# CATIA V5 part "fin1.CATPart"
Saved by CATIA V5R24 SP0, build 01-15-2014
Part number: Part2
Bounding box of the stored display mesh (mm): x -74.953 to 135, y -74.946 to 74.946, z -20 to 36.39
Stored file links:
  G:\내 드라이브\04_WORK\00_LECTURE\CAD2020\exam\models\fin1.CATPart
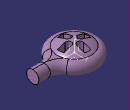
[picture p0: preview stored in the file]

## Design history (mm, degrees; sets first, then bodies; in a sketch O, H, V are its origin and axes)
AxisSystem1: origin (0, 0, 0), X (1, 0, 0), Y (0, 1, 0), Z (0, 0, 1)
Set1
  Sketch1 on YZ plane of AxisSystem1, origin (0, 0, 0), H (0, 1, 0), V (0, 0, 1)
    construction line L1 (-43.8984, 20) -> (72.6, 20)
    construction arc A1 centre (0, -63.5165) radius 100 from (55, 20) to (-55, 20) ccw
    point P3 (0, -63.5165)
    point P4 (-55, 20)
    point P5 (55, 20)
    radius A1 = 100
    distance P4 P5 = 110
    distance L1 H = 20
    horizontal: L1 H
    coincidence: P3 V, P4 L1, P5 L1
  Circle1: type CtrRad, Start 30, End 150, Center Sketch1, Support xy-plane, Radius 100, FirstDirection (1, 0, 0)
  Line1: type PtDir, RefPoint Sketch1, Direction (1, 0, 0), Start 0, End 20
  Revol1: Element1 Circle1, Line Line1, Angle1 180
  Cylinder1: Center Sketch1, Direction (0, 0, 1), Length1 178, Length2 20, Radius 55
  Split1: ToCut Revol1, Cutting Cylinder1
  Sketch2 on XY plane of AxisSystem1, origin (0, 0, 0), H (1, 0, 0), V (0, 1, 0)
    arc A1 centre (0, 0) radius 75 from (63.9829, 39.1304) to (63.9829, -39.1304) ccw
    arc A2 centre (98.1071, -60) radius 40 from (98.1071, -20) to (63.9829, -39.1304) ccw
    line L1 (135, -20) -> (98.1071, -20)
    point P2 (135, -20)
    point P3 (135, 20)
    line L2 (135, 20) -> (98.1071, 20)
    arc A3 centre (98.1071, 60) radius 40 from (98.1071, 20) to (63.9829, 39.1304) cw
    radius A1 = 75
    radius A2 = 40
    distance L1 H = 20
    distance P2 V = 135
    tangency: A2 A1, A2 L1, A3 A1, A3 L2
    horizontal: L1 H
    symmetry: P2 P3 H, L1 L2 H, A2 A3 H
  Plane1: type Offset, RefPlane YZ plane of AxisSystem1, Offset 135
  Sketch3 on Plane1, origin (135, 0, 0), H (0, 1, 0), V (0, 0, 1)
    arc A1 centre (0, 0) radius 20 from (0, 20) to (0, -20) ccw
    point P1 (0, -20)
    point P2 (0, 20)
    radius A1 = 20
    coincidence: P1 V, P2 V
  Sweep1: type Unspec, Profile Sketch3, Guide Sketch2
  Fill1: Boundary (edge of Sweep1; edge of Sweep1; edge of Sweep1)
  Plane2: type Offset, RefPlane XY plane of AxisSystem1, Offset 20
  Sketch4 on Plane2, origin (0, 0, 20), H (1, 0, 0), V (0, 1, 0)
    arc A1 centre (0, 0) radius 55 from (46.9208, -28.6957) to (46.9208, 28.6957) ccw
    point P1 (46.9208, -28.6957)
    point P2 (46.9208, 28.6957)
    reference projected line E1 (46.9208, 28.6957) -> (63.9829, 39.1304) from edge [face of Sweep1 | face of Sweep1]
    reference projected line E2 (46.9208, -28.6957) -> (63.9829, -39.1304) from edge [face of Sweep1 | face of Sweep1]
    radius A1 = 55
    coincidence: P2 E1, P1 E2
  Fill2: Boundary (edge of Sweep1; edge of Sweep1; Sketch4)
  Fill3: Boundary (edge of Sweep1; edge of Sweep1)
  Join1: Elements (Fill3; Sweep1; Fill2; Split1; Fill1)
  Sketch5 on XY plane of AxisSystem1, origin (0, 0, 0), H (1, 0, 0), V (0, 1, 0)
    arc A1 centre (0, 0) radius 45 from (10, 43.8748) to (-10, 43.8748) ccw
    arc A2 centre (0, 20) radius 10 from (-10, 20) to (10, 20) ccw
    point P1 (0, 20)
    line L1 (-10, 20) -> (-10, 43.8748)
    point P2 (-10, 20)
    line L2 (10, 20) -> (10, 43.8748)
    point P3 (10, 20)
    point P4 (-10, 20)
    point P5 (10, 20)
    radius A1 = 45
    distance P1 V = 0
    distance P1 H = 20
    radius A2 = 10
    coincidence: P2 A2, P3 A2, L2 P5, L1 P4
    tangency: L1 A2, L2 A2
    vertical: L2 V, L1 V
  Extrude1: Element1 Sketch5, Lim1 66, Lim2 62
  CircPattern1: of Extrude1, instances 4, angular step 90, axis from Z axis
  Trim1: Trimmed (Extrude1; Join1; CircPattern1)
  Trim2: Trimmed (Extrude1; Join1; CircPattern1)
Body1 (main body)
  Set2
    CloseSurface1: CloseElement Trim2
